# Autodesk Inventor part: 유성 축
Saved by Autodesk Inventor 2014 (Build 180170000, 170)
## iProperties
Created: 2026-05
Part Number: 유성 축
Material: 일반
Document SubType Name: Modeling
Designer: dg
Density: 1 g/cm^3
Appearance: 기본값
Author: dg
Author: jhkim
Creation Date: 2026-04-27
Sending System: Autodesk Inventor 2027
Preprocessor: ST-DEVELOPER v20.1
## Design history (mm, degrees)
node "유성 축1"
node "솔리드1"
node "기준1"
